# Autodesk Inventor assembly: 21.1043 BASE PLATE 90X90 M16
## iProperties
Created: 2007-03
Part Number: 21.1043 BASE PLATE 90X90 M16
Document SubType Name: Assembly
Designer: Andy Moles
Mass: 359.461 g
Surface Area: 276.678 cm^2
Volume: 118.872 cm^3
Density: 3.02393 g/cm^3
Author: Andy Moles
